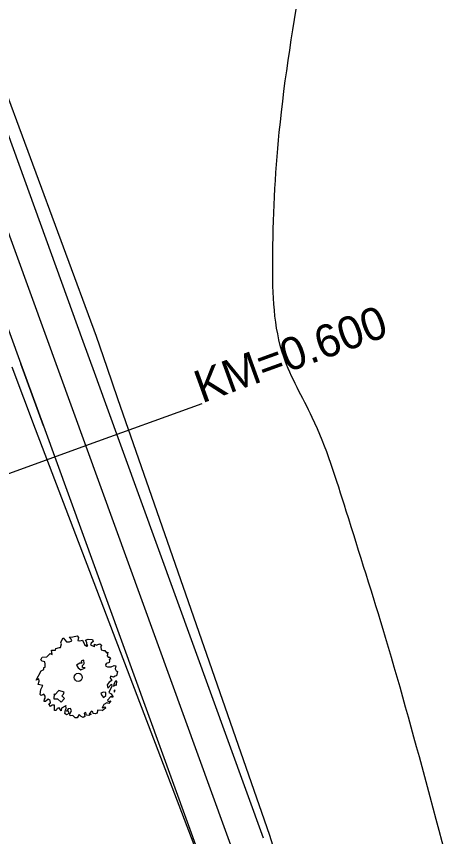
# Model space of a CAD drawing. Extents: x -475575 to -473225, y -1116053 to -1114104.
# Drawn here: x -474248.62 to -474222.45, y -1114952.74 to -1114903.05 of the extents above; entities that cross this region are included whole.
import ezdxf

# ---------------------------------------------------------------- set-up
doc = ezdxf.new("R2010")
doc.units = 0
for name, color, linetype in [('CESTN___P____KOP_N__VRH__Construction_', 7, 'Continuous'), ('IP', 7, 'Continuous'), ('POLYGONY_SITUACE_PF', 7, 'Continuous'), ('POLYGONY_SITUACE_PF_POPISY', 7, 'Continuous'), ('POLYGONY_SITUACE_PO', 7, 'Continuous'), ('Vrstevnice_vedlejsi', 7, 'Continuous')]:
    doc.layers.add(name, color=color, linetype=linetype)

msp = doc.modelspace()

# ---------------------------------------------------------------- linework, layer by layer
at = {"layer": 'CESTN___P____KOP_N__VRH__Construction_'}
for p, q in [((-474274.588, -1114840.004), (-474244.59, -1114922.733)), ((-474243.773, -1114922.437), (-474274.295, -1114839.898)), ((-474243.121, -1114924.328), (-474243.773, -1114922.437)), ((-474244.59, -1114922.733), (-474243.908, -1114924.613)), ((-474248.886, -1114924.291), (-474248.192, -1114926.167)), ((-474243.908, -1114924.613), (-474243.227, -1114926.494)), ((-474242.485, -1114926.225), (-474243.121, -1114924.328)), ((-474248.192, -1114926.167), (-474247.492, -1114928.04)), ((-474243.227, -1114926.494), (-474233.682, -1114952.817)), ((-474233.282, -1114952.672), (-474242.485, -1114926.225)), ((-474247.492, -1114928.04), (-474237.508, -1114954.204)), ((-474246.987, -1114927.857), (-474210.542, -1115028.369)), ((-474232.688, -1114954.584), (-474233.282, -1114952.672))]:
    msp.add_line(p, q, dxfattribs=at)
for points in [[(-474278.348, -1114841.367), (-474248.351, -1114924.097)], [(-474248.351, -1114924.097), (-474247.669, -1114925.977)], [(-474246.987, -1114927.857), (-474248.351, -1114924.097)], [(-474247.669, -1114925.977), (-474246.987, -1114927.857)]]:
    msp.add_lwpolyline(points, dxfattribs=at)
at = {"layer": 'IP'}
for points in [[(-474242.908, -1114944.527), (-474243.022, -1114944.676), (-474243.151, -1114944.642), (-474243.327, -1114944.733), (-474243.422, -1114944.942), (-474243.251, -1114944.876), (-474243.228, -1114944.954), (-474243.421, -1114945.133), (-474243.41, -1114945.098), (-474243.705, -1114945.085), (-474243.726, -1114945.266), (-474243.855, -1114945.306), (-474243.973, -1114945.283), (-474243.998, -1114945.179), (-474244.069, -1114945.149), (-474244.222, -1114945.301), (-474244.098, -1114945.322), (-474244.24, -1114945.415), (-474244.374, -1114945.378), (-474244.425, -1114945.225), (-474244.519, -1114945.272), (-474244.477, -1114945.465), (-474244.57, -1114945.519), (-474244.706, -1114945.461), (-474244.82, -1114945.343), (-474244.948, -1114945.556), (-474245.071, -1114945.551), (-474245.2, -1114945.409), (-474245.355, -1114945.424), (-474245.379, -1114945.316), (-474245.288, -1114945.125), (-474245.336, -1114944.981), (-474245.495, -1114945.006), (-474245.579, -1114945.142), (-474245.495, -1114945.131), (-474245.458, -1114945.199), (-474245.44, -1114945.289), (-474245.593, -1114945.361), (-474245.681, -1114945.296), (-474245.651, -1114945.071), (-474245.601, -1114944.993), (-474245.628, -1114944.802), (-474245.636, -1114944.822), (-474245.885, -1114944.963), (-474245.906, -1114945.126), (-474246.029, -1114944.938), (-474246.15, -1114944.976), (-474246.206, -1114945.109), (-474246.303, -1114945.106), (-474246.32, -1114944.78), (-474246.479, -1114944.773), (-474246.557, -1114944.864), (-474246.65, -1114944.701), (-474246.55, -1114944.632), (-474246.581, -1114944.495), (-474246.705, -1114944.414), (-474246.853, -1114944.556), (-474246.94, -1114944.558), (-474246.92, -1114944.423), (-474246.873, -1114944.352), (-474246.879, -1114944.231), (-474246.962, -1114944.124), (-474247.121, -1114944.201), (-474247.181, -1114944.135), (-474247.148, -1114943.825), (-474247.026, -1114943.596), (-474247.297, -1114943.537), (-474247.242, -1114943.328), (-474247.258, -1114943.182), (-474247.427, -1114943.275), (-474247.127, -1114942.698), (-474246.965, -1114942.629), (-474246.959, -1114942.499), (-474246.884, -1114942.472), (-474246.881, -1114942.291), (-474246.908, -1114942.154), (-474247.064, -1114942.125), (-474247.134, -1114942.038), (-474247.054, -1114941.882), (-474246.771, -1114941.85), (-474246.569, -1114941.642), (-474246.457, -1114941.702), (-474246.502, -1114941.458), (-474246.257, -1114941.441), (-474246.23, -1114941.353), (-474246.005, -1114941.29), (-474245.952, -1114941.29), (-474245.89, -1114941.059), (-474245.928, -1114940.993), (-474245.869, -1114940.835), (-474245.789, -1114940.709), (-474245.579, -1114940.945), (-474245.412, -1114940.951), (-474245.27, -1114940.883), (-474245.305, -1114940.774), (-474245.432, -1114940.667), (-474245.194, -1114940.637), (-474244.947, -1114940.577), (-474244.86, -1114940.674), (-474244.901, -1114940.863), (-474244.777, -1114940.882), (-474244.626, -1114940.85), (-474244.493, -1114941.108), (-474244.379, -1114941.206), (-474244.285, -1114941.188), (-474244.362, -1114941.09), (-474244.362, -1114940.976), (-474244.446, -1114940.841), (-474244.272, -1114940.787), (-474244.019, -1114940.802), (-474243.97, -1114940.922), (-474244.091, -1114941.025), (-474244.131, -1114941.134), (-474243.92, -1114941.236), (-474243.885, -1114941.246), (-474243.883, -1114941.091), (-474243.765, -1114941.15), (-474243.692, -1114941.105), (-474243.561, -1114941.062), (-474243.459, -1114941.152), (-474243.503, -1114941.255), (-474243.486, -1114941.434), (-474243.348, -1114941.478), (-474243.262, -1114941.46), (-474243.174, -1114941.618), (-474243.081, -1114941.577), (-474243.124, -1114941.783), (-474243.072, -1114941.874), (-474242.968, -1114941.869), (-474242.923, -1114942.004), (-474242.993, -1114942.018), (-474242.986, -1114942.1), (-474243.012, -1114942.188), (-474243.051, -1114942.222), (-474243.117, -1114942.237), (-474243.177, -1114942.279), (-474243.219, -1114942.333), (-474243.195, -1114942.417), (-474243.095, -1114942.453), (-474242.875, -1114942.454), (-474242.704, -1114942.38), (-474242.6, -1114942.389), (-474242.63, -1114942.571), (-474242.586, -1114942.701), (-474242.508, -1114942.732), (-474242.569, -1114943.005), (-474242.637, -1114943.027), (-474242.732, -1114943.089), (-474242.93, -1114943.034), (-474242.937, -1114943.133), (-474242.85, -1114943.288), (-474243.008, -1114943.386), (-474243.118, -1114943.552), (-474243.075, -1114943.754), (-474242.852, -1114943.5), (-474242.84, -1114943.635), (-474243.017, -1114944.013), (-474242.882, -1114944.095), (-474242.782, -1114944.263), (-474242.802, -1114944.309), (-474242.905, -1114944.26), (-474243.109, -1114944.469), (-474243.066, -1114944.564)], [(-474244.637, -1114942.235), (-474244.779, -1114942.235), (-474244.981, -1114942.364), (-474244.884, -1114942.516), (-474244.71, -1114942.643), (-474244.45, -1114942.521), (-474244.626, -1114942.49), (-474244.608, -1114942.388), (-474244.538, -1114942.291), (-474244.507, -1114942.25), (-474244.53, -1114942.062), (-474244.624, -1114942.074), (-474244.7, -1114942.124), (-474244.67, -1114942.197)], [(-474242.617, -1114943.329), (-474242.729, -1114943.506), (-474242.744, -1114943.621), (-474242.59, -1114943.547), (-474242.566, -1114943.579), (-474242.53, -1114943.332)], [(-474245.72, -1114944.003), (-474246.048, -1114943.89), (-474246.289, -1114944.151), (-474246.343, -1114944.101), (-474246.349, -1114944.391), (-474246.13, -1114944.397), (-474245.908, -1114944.605), (-474245.699, -1114944.384), (-474245.868, -1114944.224), (-474245.77, -1114944.12)], [(-474243.197, -1114944.011), (-474243.353, -1114943.984), (-474243.503, -1114944.061), (-474243.452, -1114944.199), (-474243.348, -1114944.309), (-474243.211, -1114944.196)], [(-474242.65, -1114943.854), (-474242.729, -1114943.93), (-474242.691, -1114943.978), (-474242.656, -1114943.954)]]:
    msp.add_lwpolyline(points, close=True, dxfattribs=at)
msp.add_circle((-474244.876, -1114943.098), 0.247, dxfattribs=at)
at = {"layer": 'POLYGONY_SITUACE_PF'}
msp.add_lwpolyline([(-474251.476, -1114931.612), (-474244.425, -1114929.056), (-474237.374, -1114926.499)], dxfattribs=at)
at = {"layer": 'POLYGONY_SITUACE_PO'}
msp.add_lwpolyline([(-474033.93, -1115484.017), (-474028.81, -1115469.55), (-474027.706, -1115465.586), (-474027.155, -1115461.509), (-474027.167, -1115457.394), (-474027.702, -1115449.947), (-474028.133, -1115446.706), (-474028.952, -1115443.542), (-474030.148, -1115440.499), (-474155.776, -1115170.193), (-474159.336, -1115162.232), (-474162.663, -1115154.172), (-474165.754, -1115146.018), (-474287.504, -1114810.25), (-474291.915, -1114795.876)], dxfattribs=at)
at = {"layer": 'Vrstevnice_vedlejsi'}
for points in [[(-474198.341, -1114669.49), (-474196.681, -1114672.256), (-474195.18, -1114674.653), (-474193.836, -1114676.681), (-474192.651, -1114678.341), (-474192.443, -1114683.526), (-474193.214, -1114692.237), (-474194.962, -1114704.473), (-474196.31, -1114712.997), (-474197.258, -1114717.807), (-474197.807, -1114718.903), (-474198.355, -1114720.033), (-474198.903, -1114721.196), (-474199.452, -1114722.393), (-474202.29, -1114724.764), (-474207.417, -1114728.309), (-474214.834, -1114733.029), (-474221.352, -1114738.648), (-474226.971, -1114745.166), (-474231.691, -1114752.583), (-474235.037, -1114757.727), (-474237.009, -1114760.598), (-474237.607, -1114761.196), (-474238.205, -1114762.022), (-474238.804, -1114763.076), (-474239.402, -1114764.358), (-474242.028, -1114769.031), (-474246.681, -1114777.093), (-474253.362, -1114788.547), (-474258.559, -1114799.152), (-474262.27, -1114808.908), (-474264.497, -1114817.816), (-474266.676, -1114825.23), (-474268.807, -1114831.15), (-474270.889, -1114835.575), (-474272.278, -1114842.188), (-474272.972, -1114850.991), (-474272.972, -1114861.981), (-474273.054, -1114870.089), (-474273.218, -1114875.314), (-474273.465, -1114877.657), (-474273.273, -1114882.608), (-474272.641, -1114890.167), (-474271.571, -1114900.334), (-474271.061, -1114908.167), (-474271.11, -1114913.667), (-474271.719, -1114916.834), (-474271.646, -1114922.058), (-474270.891, -1114929.339), (-474269.454, -1114938.678), (-474268.091, -1114946.236), (-474266.802, -1114952.012), (-474265.586, -1114956.006), (-474264.292, -1114960.893), (-474262.92, -1114966.673), (-474261.469, -1114973.346), (-474259.897, -1114980.014), (-474258.202, -1114986.679), (-474256.386, -1114993.34), (-474254.916, -1115000.31), (-474253.793, -1115007.591), (-474253.017, -1115015.182), (-474252.121, -1115021.507), (-474251.104, -1115026.568), (-474249.968, -1115030.364), (-474249.22, -1115033.873), (-474248.86, -1115037.095), (-474248.889, -1115040.031), (-474248.926, -1115042.279), (-474248.97, -1115043.838), (-474249.022, -1115044.709), (-474249.185, -1115045.346), (-474249.46, -1115045.75), (-474249.845, -1115045.92), (-474250.053, -1115046.628), (-474250.085, -1115047.873), (-474249.939, -1115049.656), (-474250.24, -1115054.341), (-474250.987, -1115061.928), (-474252.18, -1115072.418), (-474252.552, -1115080.569), (-474252.103, -1115086.383), (-474250.833, -1115089.859), (-474248.888, -1115093.001), (-474246.267, -1115095.808), (-474242.971, -1115098.281), (-474237.53, -1115101.018), (-474229.942, -1115104.018), (-474220.207, -1115107.282), (-474212.554, -1115110.016), (-474206.982, -1115112.221), (-474203.491, -1115113.895), (-474200.507, -1115114.848), (-474198.031, -1115115.078), (-474196.062, -1115114.586), (-474193.634, -1115114.914), (-474190.746, -1115116.062)], [(-474106.724, -1115139.906), (-474105.975, -1115134.747), (-474104.91, -1115130.242), (-474103.528, -1115126.392), (-474101.829, -1115123.196), (-474101.248, -1115119.409), (-474101.786, -1115115.032), (-474103.442, -1115110.065), (-474106.201, -1115105.465), (-474110.065, -1115101.234), (-474115.032, -1115097.37), (-474120.595, -1115093.294), (-474126.753, -1115089.004), (-474133.506, -1115084.502), (-474139.856, -1115081.154), (-474145.801, -1115078.961), (-474151.342, -1115077.922), (-474155.382, -1115077.318), (-474157.922, -1115077.148), (-474158.961, -1115077.413), (-474159.927, -1115077.355), (-474160.82, -1115076.975), (-474161.64, -1115076.273), (-474163.375, -1115076.297), (-474166.027, -1115077.047), (-474169.593, -1115078.523), (-474174.953, -1115080.253), (-474182.107, -1115082.237), (-474191.053, -1115084.473), (-474198.277, -1115085.36), (-474203.777, -1115084.898), (-474207.554, -1115083.087), (-474210.582, -1115078.783), (-474212.862, -1115071.987), (-474214.394, -1115062.7), (-474215.425, -1115054.98), (-474215.955, -1115048.829), (-474215.985, -1115044.245), (-474215.583, -1115041.048), (-474214.749, -1115039.236), (-474213.484, -1115038.81), (-474212.393, -1115038.422), (-474211.477, -1115038.073), (-474210.736, -1115037.762), (-474210.235, -1115036.623), (-474209.974, -1115034.657), (-474209.953, -1115031.862), (-474210.087, -1115026.769), (-474210.376, -1115019.378), (-474210.819, -1115009.689), (-474212.181, -1114998.785), (-474214.462, -1114986.667), (-474217.662, -1114973.333), (-474220.697, -1114961.225), (-474223.567, -1114950.342), (-474226.271, -1114940.683), (-474228.65, -1114933.019), (-474230.705, -1114927.35), (-474232.434, -1114923.675), (-474233.1, -1114917.916), (-474232.704, -1114910.072), (-474231.244, -1114900.144), (-474229.766, -1114892.391), (-474228.27, -1114886.811), (-474226.756, -1114883.405), (-474225.554, -1114878.524), (-474224.663, -1114872.166), (-474224.082, -1114864.332), (-474222.871, -1114857.276), (-474221.027, -1114850.999), (-474218.553, -1114845.499), (-474216.392, -1114840.557), (-474214.547, -1114836.172), (-474213.015, -1114832.344), (-474210.719, -1114828.319), (-474207.656, -1114824.099), (-474203.828, -1114819.682), (-474200.394, -1114815.041), (-474197.354, -1114810.176), (-474194.708, -1114805.088), (-474192.13, -1114800), (-474189.62, -1114794.912), (-474187.178, -1114789.824), (-474182.801, -1114780.435), (-474176.49, -1114766.746), (-474168.245, -1114748.757), (-474162.295, -1114736.021), (-474158.639, -1114728.54), (-474157.277, -1114726.312), (-474156.001, -1114724.373), (-474154.81, -1114722.723), (-474153.704, -1114721.361), (-474151.414, -1114718.384), (-474147.941, -1114713.791), (-474143.284, -1114707.582), (-474139.388, -1114701.068), (-474136.252, -1114694.249)], [(-474227.218, -1115164.851), (-474226.448, -1115162.426), (-474227.525, -1115159.571), (-474230.451, -1115156.287), (-474235.226, -1115152.573), (-474240.399, -1115148.881), (-474245.971, -1115145.211), (-474251.942, -1115141.562), (-474256.818, -1115137.139), (-474260.6, -1115131.942), (-474263.287, -1115125.971), (-474265.918, -1115121.36), (-474268.492, -1115118.11), (-474271.011, -1115116.221), (-474273.409, -1115112.993), (-474275.686, -1115108.429), (-474277.843, -1115102.526), (-474279.974, -1115096.744), (-474282.078, -1115091.082), (-474284.156, -1115085.541), (-474285.812, -1115080.883), (-474287.047, -1115077.109), (-474287.86, -1115074.218), (-474288.244, -1115068.81), (-474288.198, -1115060.885), (-474287.724, -1115050.442), (-474287.488, -1115042.595), (-474287.491, -1115037.342), (-474287.732, -1115034.684), (-474288.91, -1115029.354), (-474291.024, -1115021.351), (-474294.074, -1115010.675), (-474297.009, -1115000.754), (-474299.828, -1114991.588), (-474302.532, -1114983.176), (-474304.676, -1114975.928), (-474306.261, -1114969.843), (-474307.286, -1114964.921), (-474309.265, -1114957.199), (-474312.198, -1114946.677), (-474316.084, -1114933.354), (-474318.675, -1114924.468), (-474319.971, -1114920.02), (-474319.973, -1114920.01), (-474319.977, -1114919.992), (-474319.984, -1114919.965), (-474319.992, -1114919.931), (-474321.301, -1114916.779), (-474323.911, -1114910.509), (-474327.823, -1114901.121), (-474333.571, -1114893.897), (-474341.156, -1114888.835), (-474350.578, -1114885.936), (-474361.246, -1114883.666), (-474373.16, -1114882.025), (-474386.32, -1114881.012), (-474395.152, -1114880.336), (-474399.654, -1114879.994), (-474399.827, -1114879.989), (-474403.877, -1114879.477), (-474411.805, -1114878.46), (-474423.609, -1114876.937), (-474431.988, -1114875.62), (-474436.942, -1114874.51), (-474438.471, -1114873.607), (-474443.932, -1114869.371), (-474453.324, -1114861.802), (-474466.647, -1114850.901), (-474475.533, -1114843.63), (-474479.981, -1114839.989), (-474479.99, -1114839.978), (-474480.008, -1114839.975), (-474480.035, -1114839.978), (-474480.069, -1114839.989), (-474480.092, -1114840.008), (-474480.104, -1114840.035), (-474480.104, -1114840.069), (-474483.152, -1114844.525), (-474489.247, -1114853.403), (-474498.39, -1114866.701), (-474505.505, -1114879.646), (-474510.592, -1114892.237), (-474513.651, -1114904.473), (-474515.798, -1114912.997), (-474517.033, -1114917.807), (-474517.355, -1114918.903), (-474517.71, -1114919.879), (-474518.097, -1114920.733), (-474518.517, -1114921.467), (-474518.841, -1114922.054), (-474519.069, -1114922.494), (-474519.202, -1114922.788), (-474519.513, -1114923.611), (-474520.002, -1114924.961), (-474520.669, -1114926.839), (-474521.912, -1114930.34), (-474523.73, -1114935.464)]]:
    msp.add_spline(points, degree=3, dxfattribs=at)

# ---------------------------------------------------------------- texts
at = {"layer": 'POLYGONY_SITUACE_PF_POPISY'}
msp.add_text('KM=0.600', height=1.9765, rotation=19.9307, dxfattribs=at).set_placement((-474237.386, -1114926.503))

doc.saveas('drawing.dxf')
